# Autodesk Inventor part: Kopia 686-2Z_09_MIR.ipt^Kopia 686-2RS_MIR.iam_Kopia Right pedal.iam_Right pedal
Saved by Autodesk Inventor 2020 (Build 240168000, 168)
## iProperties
Created: 2017-10
Part Number: Kopia 686-2Z_09_MIR.ipt^Kopia 686-2RS_MIR.iam_Kopia Right pedal.iam_Right pedal
Material: Ogólny
Document SubType Name: Modeling
Designer: Tomasz
Density: 1 g/cm^3
Appearance: Domyślna
Sending System: SolidWorks 2017
Last Author: Tomasz
Last Saved: 2017-10-01
Author: Tomasz
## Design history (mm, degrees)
